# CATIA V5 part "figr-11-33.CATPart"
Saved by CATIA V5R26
Part number: Part1
Bounding box of the stored display mesh (mm): x -120 to 40, y -443 to 443, z -443 to 443
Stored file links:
  D:\_Deepak\CATIA\CATIA V5-6R2016_Deepak\Resources\Part files\Partfiles\c11_catia_v5_6r2016_prt\figr-11-33.CATPart
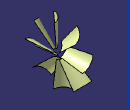
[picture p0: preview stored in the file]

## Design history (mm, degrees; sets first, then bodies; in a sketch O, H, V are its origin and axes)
Set1
  Plane1: type Offset, RefPlane xy-plane, Offset 443
  Sketch1 on Plane1, origin (0, 0, 443), H (1, 0, 0), V (0, 1, 0)
    arc A1 centre (51.3551, -160.9813) radius 171.358 from (40, 10) to (-120, -160) ccw
  Loft1: Sections (Sketch3; Sketch1)
  Sketch2 on zx-plane, origin (0, 0, 0), H (-1, 0, 0), V (0, 0, 1)
    line L1 (-270, 0) -> (280, 0)
    point P1 (-270, 0)
    coincidence: P1 H
    horizontal: L1 H
  Rotate1: ToTransfor Loft1, Axis Sketch2, Angle 45
  Rotate2: ToTransfor Loft1, Axis Sketch2, Angle 90 {= Rotate1.Angle * 2}
  Rotate3: ToTransfor Loft1, Axis Sketch2, Angle 135 {= Rotate1.Angle * 3}
  Rotate4: ToTransfor Loft1, Axis Sketch2, Angle 180 {= Rotate1.Angle * 4}
  Rotate5: ToTransfor Loft1, Axis Sketch2, Angle 225 {= Rotate1.Angle * 5}
  Rotate6: ToTransfor Loft1, Axis Sketch2, Angle 270 {= Rotate1.Angle * 6}
  Rotate7: ToTransfor Loft1, Axis Sketch2, Angle 315 {= Rotate1.Angle * 7}
  Rotate8: ToTransfor Loft1, Axis Sketch2, Angle 360 {= Rotate1.Angle * 8}
  Rotate9: ToTransfor Loft1, Axis Sketch2, Angle 405 {= Rotate1.Angle * 9}
Body1 (main body)
  Sketch3 on Plane2, origin (0, 0, 67), H (1, 0, 0), V (0, 1, 0)
    point P1 (-100, 0)
    arc A1 centre (50, -150) radius 158.1139 from (0, 0) to (-100, -100) ccw
Set2
  Plane2: type Offset, RefPlane xy-plane, Offset 67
